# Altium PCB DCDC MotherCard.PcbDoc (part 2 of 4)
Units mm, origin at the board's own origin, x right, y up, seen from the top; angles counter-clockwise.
Board outline 252.5 x 130 mm, 6 copper layers (Top Layer, Layer 2, Layer 3, Layer 4, Layer 5, Bottom Layer), stack 1.582 mm thick; 322 components, 189 nets, 1077 pads, 1461 vias.
Unrouted connection lines stored in the file: 2.
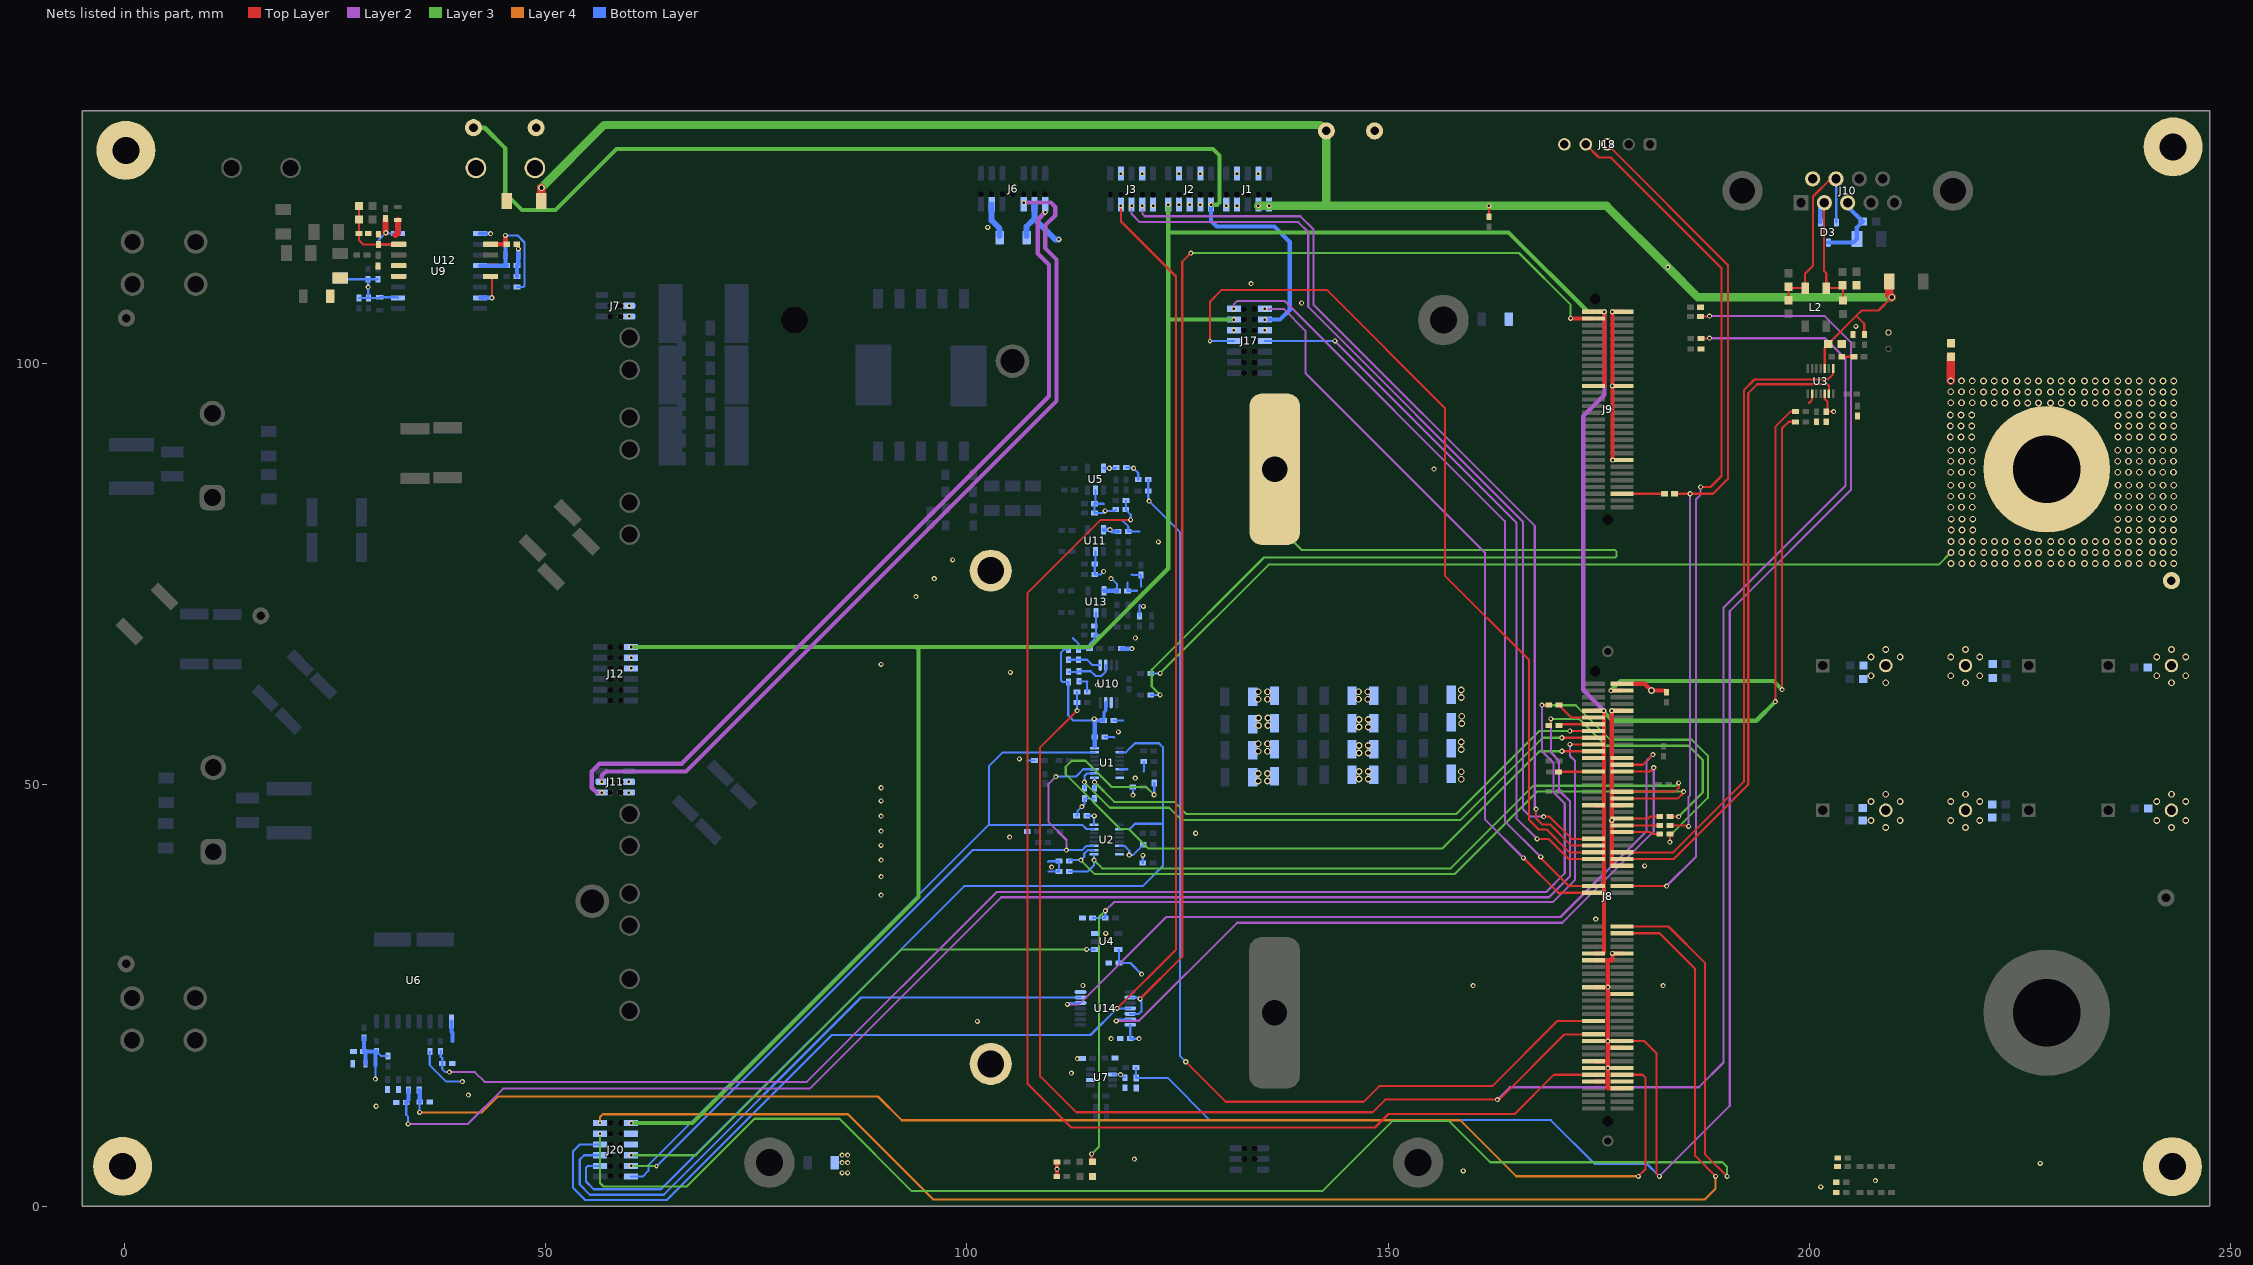
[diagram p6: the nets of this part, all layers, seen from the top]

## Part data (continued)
C41 C75 C80 C83: library part CMP-0076705-3, "CAP, CERM, 1 µF, 25 V,+/- 10%, X7R, AEC-Q200 Grade 1, 0603", Cap_Case=1.6x0.8x0.8mm, Manufacturer=TDK, Supplier Part Number 1=445-6931-1-ND, TempCo=X7R, Tolerance_%=10%, Value2=25V, ValueDisplayed=1µF
C46 C47 C72: library part CMP-0124726-1, "1 µF ±20% 700V Ceramic Capacitor Stacked SMD, 4 J-Lead", Digikey Part Number=495-B58035U7105M052CT-ND, Manufacturer=TDK, Mouser Part Number=871-B58035U7105M052, Operating Temperature Range="-40°C to +150°C", Tolerance_%=20%, ValueDisplayed=1uF
C51 C69 C70 C71 C81 C82 C85 C100 C104 C107 C108: library part CMP-0006357-2, "CAP, CERM, 2200 pF, 50 V, +/- 10%, X7R, AEC-Q200 Grade 1, 0402", Cap_Case=0402, Manufacturer=MuRata, Supplier Part Number 1=490-4914-1-ND, TempCo=X7R, Tolerance_%=10%, Value1=Unknown, Value2=50V, ValueDisplayed=2200pF
C73 C86 C97: library part CMP-0006324-2, "CAP, CERM, 0.01 uF, 50 V, +/- 10%, X7R, AEC-Q200 Grade 1, 0402", Cap_Case=0402, Manufacturer=TDK, Supplier Part Number 1=445-6893-1-ND, TempCo=X7R, Tolerance_%=10%, Value1="0.333065 ohm", Value2=50V, ValueDisplayed=0.01uF
D1: library part CMP-0002842-2, "LED, Red, SMD", Color=red, Manufacturer=Lite-On, Power_TotalModule=62.5mW, Value1=0.0625W, Value2=2V
D2: library part CMP-0002827-3, "LED, Green, SMD", Color=green, Manufacturer=Lite-On, Power_TotalModule=100mW, Value1=0.1W, Value2=2.1V
D3: library part CMP-0005919-2, "Diode, TVS, Bi, 24 V, SOT-23", Manufacturer="ON Semiconductor", Power_W=350mW, Supplier Part Number 1=NUP2105LT1GOSCT-ND, Value1=0.35W
D4 D5: library part CMP-0028855-2, "Diode, Schottky, 40 V, 3 A, AEC-Q101, SMAF", Manufacturer="Fairchild Semiconductor", Value1=3A, Value2=0.5V
D6 D7 D8 D9: library part CMP-0094495-1, "Diode Schottky 30 V 1A Surface Mount SOD-123", Digikey Part Number=MBR130T3GOSCT-ND, Forward Current=1A, Manufacturer=onsemi, Max Surge Forward Current=5.5A, Mouser Part Number=863-MBR130T3G, Operating Temperature Range="-65°C to +125°C", Peak Reverse Current=60uA
D10: library part CMP-0005910-2, "Diode, Zener, 4.7 V, 150 mW, AEC-Q101, SOD-523", Manufacturer=Rohm, Power_W=150mW, Supplier Part Number 1=78Y8306, Value1=0.15W
D11 D12 D13 D14: library part CMP-0028768-3, "Diode, Schottky, 30 V, 0.2 A, AEC-Q101, SOD-523", Manufacturer="ON Semiconductor", Value1=0.2A, Value2=0.5V
J1 J2 J3: library part CMP-0088850-1, "10 Position Receptacle Connector  Surface Mount", Current_A=2.9A, Digikey Part Number=SAM1226-05-ND, Manufacturer=SAMTEC, Mouser Part Number=200-FLE10501GDV, Operating Temperature Range="-55°C to +125°C"
J4 J5: library part CMP-0055125-1, "TERMINAL SCREW PC 30AMP, TH", Manufacturer=Keystone, Supplier Part Number 1=36-8199-ND
J6 J17: library part CMP-0075566-1, "Receptacle, 1.27mm, 7x2, Gold, SMT", Manufacturer=Samtec, Supplier Part Number 1=SAM1226-07-ND
J7 J11 J13: library part CMP-0055704-1, "Receptacle, 1.27mm, 3x2, Gold, SMT", Color=Black, Current_A=3.3A, Manufacturer=Samtec, Supplier Part Number 1=SAM1154-03-ND, Voltage_V=240V
J8: library part CMP-0003814-2, "C2000 controlCARD-120HSEC connector, SMT", Manufacturer=Samtec
J9: library part CMP-0003859-2, "C2000 controlCARD-180HSEC (60-pin addon) connector, SMT", Manufacturer=Samtec
J10: library part CMP-0074955-1, "CONN DB9 FEMALE R/A SOLDER TH", Manufacturer=NorComp, Supplier Part Number 1=182-909FE-ND
J12 J20: library part CMP-0075577-1, "Receptacle, 1.27mm, 6x2, Gold, SMT", Current_A=2A, Manufacturer=Samtec, Supplier Part Number 1=99P6807
J18: library part CMP-0054624-1, "Header, 2.54mm, 5x1, Gold, R/A, TH", Color=Black, Current_A=3A, Manufacturer="Sullins Connector Solutions", Supplier Part Number 1=S1111EC-05-ND
L1: library part CMP-0003317-1, "Ferrite Bead, 600 ohm @ 100 MHz, 0.5 A, 0402", Manufacturer=MuRata, Supplier Part Number 1=490-5441-1-ND, Value1="0.34 ohm", Value2=0.5A, ValueDisplayed="600 ohm"
L2: library part CMP-0062430-2, "Inductor, Ferrite, 100 uH, 0.15 A, 2 ohm, SMD", Manufacturer=TDK, Supplier Part Number 1=445-3959-1-ND, Value1="2 ohm", Value2=0.15A, ValueDisplayed=100uH
LBL1: library part CMP-0003625-1, "Thermal Transfer Printable Labels, 0.650\" W x 0.200\" H - 10,000 per roll", Manufacturer=Brady, Supplier Part Number 1=97C5133
Logo1: library part CMP-0074844-1
LOGO2: library part CMP-0074835-1, "IEC 61010-1 High Voltage Warning"
Logo3: library part CMP-0074847-1, "FCC_disclaimer"
Logo4: library part CMP-0074769-1
LOGO5 LOGO6: library part CMP-0074837-1, "IEC 61010-1 Hot Surface Warning"
R1 R15 R16 R19 R26 R117 R118 R120 R121 R122 R123 R124 R126 R127 R128 R129 R132 R133: library part CMP-0080698-1, "RES, 0, 0%, 1 W, AEC-Q200 Grade 0, 2512", Manufacturer=Kamaya, Power_W=1W, Supplier Part Number 1=791-RMC1JPTE, Tolerance_%=0%, Value_Code=0
R2 R3: library part CMP-0018576-3, "RES, 10 k, 5%, 0.25 W, AEC-Q200 Grade 0, 1206", Manufacturer=Vishay-Dale, Power_W=250mW, Supplier Part Number 1=541-10KECT-ND, TempCo="200 ppm/C", Tolerance_%=5%, Value2=0.25W, Value_Code=10k0, ValueDisplayed=10k
R4 R5 R6 R7: library part CMP-0018574-3, "RES, 100 k, 5%, 0.25 W, AEC-Q200 Grade 0, 1206", Manufacturer=Vishay-Dale, Power_W=250mW, Supplier Part Number 1=541-100KECT-ND, TempCo="200 ppm/C", Tolerance_%=5%, Value2=0.25W, Value_Code=100k
R8 R9 R54 R78: library part CMP-0026786-1, "RES, 7.50 k, 0.1%, 0.063 W, AEC-Q200 Grade 0, 0402", Manufacturer=Panasonic, Power_W=63mW, Supplier Part Number 1=P7.5KDCCT-ND, TempCo="25 ppm/C", Tolerance_%=0.1%, Value2=0.063W, Value_Code=7k50, ValueDisplayed=7.50k
R10 R12 R13 R41 R46 R48 R49 R51 R53 R55 R57 R63 R64 R68 R70 R71 R72 R80 R82 R83 R98 R107: library part CMP-0026822-3, "RES, 0, 5%, 0.063 W, AEC-Q200 Grade 0, 0402", Manufacturer=Vishay-Dale, Power_W=63mW, Supplier Part Number 1=541-0.0JCT-ND, TempCo="200 ppm/C", Tolerance_%=5%, Value2=0.063W, Value_Code=0000, ValueDisplayed=0
R11 R17 R22: library part CMP-0023343-3, "RES, 0, 1%, 0.1 W, AEC-Q200 Grade 0, 0603", Manufacturer="Stackpole Electronics Inc", Power_W=100mW, Supplier Part Number 1=RMCF0603ZT0R00CT-ND, TempCo=ppm/C, Tolerance_%=1%, Value2=0.1W, Value_Code=0
R14 R50 R60 R61 R65 R66 R79 R97 R99 R100 R103 R130 R134 R135 R136 R137: library part CMP-0026748-1, "RES, 10.0 k, 1%, 0.063 W, AEC-Q200 Grade 0, 0402", Manufacturer="KOA Speer", Power_W=63mW, Supplier Part Number 1=660-RK73H1ETTP1002F, TempCo="100 ppm/C", Tolerance_%=1%, Value2=0.063W, Value_Code=10k0, ValueDisplayed=10.0k
R18 R21: library part CMP-0022532-4, "RES, 60.4 k, 1%, 0.1 W, AEC-Q200 Grade 0, 0603", Manufacturer=Vishay-Dale, Power_W=100mW, Supplier Part Number 1=541-60.4KHCT-ND, TempCo="100 ppm/C", Tolerance_%=1%, Value2=0.1W, Value_Code=60k4, ValueDisplayed=60.4k
R20 R33 R77 R119: library part CMP-0093609-1, "0Ω ±0 0.25W 1206 Thick Film Chip Resistor AEC-Q200 compliant", Manufacturer="Stackpole Electronics", Operating Temperature Range="-55°C to +155°C", Power_W=250mW
R23: library part CMP-0022138-4, "RES, 1.00 M, 1%, 0.1 W, AEC-Q200 Grade 0, 0603", Manufacturer=Vishay-Dale, Power_W=100mW, Supplier Part Number 1=541-1.00MHCT-ND, TempCo="100 ppm/C", Tolerance_%=1%, Value2=0.1W, Value_Code=1M00, ValueDisplayed=1.00M
R24 R32 R101 R102: library part CMP-0026676-1, "RES, 2.00 k, 1%, 0.1 W, AEC-Q200 Grade 0, 0402", Manufacturer=Panasonic, Power_W=100mW, Supplier Part Number 1=P2.00KLCT-ND, TempCo="100 ppm/C", Tolerance_%=1%, Value2=0.1W, Value_Code=2k00, ValueDisplayed=2.00k
R25 R31 R67 R87 R96 R114: library part CMP-0026071-3, "RES, 1.00 k, 1%, 0.063 W, AEC-Q200 Grade 0, 0402", Manufacturer=Vishay-Dale, Power_W=63mW, Supplier Part Number 1=541-1.00KLCT-ND, TempCo="100 ppm/C", Tolerance_%=1%, Value2=0.063W, Value_Code=1k00, ValueDisplayed=1.00k
R27 R40 R47 R52 R62 R73 R74 R76 R112 R113: library part CMP-0026764-1, "RES, 10.0, 1%, 0.063 W, AEC-Q200 Grade 0, 0402", Manufacturer="Stackpole Electronics Inc", Power_W=63mW, Supplier Part Number 1=RMCF0402JT10R0CT-ND, TempCo="100 ppm/C", Tolerance_%=1%, Value2=0.063W, Value_Code=10R0, ValueDisplayed=10.0
R28 R29 R39: library part CMP-0016648-3, "RES, 15.0, 1%, 0.25 W, AEC-Q200 Grade 0, 1206", Manufacturer=Vishay-Dale, Power_W=250mW, Supplier Part Number 1=541-15.0FCT-ND, TempCo="100 ppm/C", Tolerance_%=1%, Value2=0.25W, Value_Code=15R0, ValueDisplayed=15.0
R30 R37 R38: library part CMP-0022268-4, "RES, 2.00 k, 1%, 0.1 W, AEC-Q200 Grade 0, 0603", Manufacturer=Vishay-Dale, Power_W=100mW, Supplier Part Number 1=541-2.00KHCT-ND, TempCo="100 ppm/C", Tolerance_%=1%, Value2=0.1W, Value_Code=2k00, ValueDisplayed=2.00k
R34 R35 R36 R110 R115 R125 R131: library part CMP-0025951-3, "RES, 100, 1%, 0.063 W, AEC-Q200 Grade 0, 0402", Manufacturer=Vishay-Dale, Power_W=63mW, Supplier Part Number 1=541-100LCT-ND, TempCo="100 ppm/C", Tolerance_%=1%, Value2=0.063W, Value_Code=100R, ValueDisplayed=100
R42: library part CMP-0026395-2, "RES, 47.5 k, 1%, 0.063 W, AEC-Q200 Grade 0, 0402", Manufacturer=Vishay-Dale, Power_W=63mW, Supplier Part Number 1=541-47.5KLCT-ND, TempCo="100 ppm/C", Tolerance_%=1%, Value2=0.063W, Value_Code=47k5, ValueDisplayed=47.5k
R43 R44 R45 R104 R105 R106: library part CMP-0017741-3, "RES, 845 k, 1%, 0.25 W, AEC-Q200 Grade 0, 1206", Manufacturer=Panasonic, Power_W=250mW, Supplier Part Number 1=P845KFCT-ND, TempCo="100 ppm/C", Tolerance_%=1%, Value2=0.25W, Value_Code=845k
R56 R108: library part CMP-0017234-3, "RES, 9.09 k, 1%, 0.25 W, AEC-Q200 Grade 0, 1206", Manufacturer=Vishay-Dale, Power_W=250mW, Supplier Part Number 1=541-9.09KFCT-ND, TempCo="100 ppm/C", Tolerance_%=1%, Value2=0.25W, Value_Code=9k09, ValueDisplayed=9.09k
R58 R59 R69 R75 R109 R116: library part CMP-0026027-3, "RES, 15.0 k, 1%, 0.063 W, AEC-Q200 Grade 0, 0402", Manufacturer=Vishay-Dale, Power_W=63mW, Supplier Part Number 1=541-15.0KLCT-ND, TempCo="100 ppm/C", Tolerance_%=1%, Value2=0.063W, Value_Code=15k0, ValueDisplayed=15.0k
R81: library part CMP-0026404-2, "RES, 49.9, 1%, 0.063 W, AEC-Q200 Grade 0, 0402", Manufacturer=Vishay-Dale, Power_W=63mW, Supplier Part Number 1=541-49.9LCT-ND, TempCo="100 ppm/C", Tolerance_%=1%, Value2=0.063W, Value_Code=49R9, ValueDisplayed=49.9
R91 R95: library part CMP-0026750-1, "RES, 3.30 k, 1%, 0.063 W, AEC-Q200 Grade 0, 0402", Manufacturer="KOA Speer", Power_W=63mW, Supplier Part Number 1=660-RK73H1ETTP3301F, TempCo="100 ppm/C", Tolerance_%=1%, Value2=0.063W, Value_Code=3k30, ValueDisplayed=3.30k
R92 R111: library part CMP-0026337-2, "RES, 3.65 k, 1%, 0.063 W, AEC-Q200 Grade 0, 0402", Manufacturer=Vishay-Dale, Power_W=63mW, Supplier Part Number 1=541-3.65KLCT-ND, TempCo="100 ppm/C", Tolerance_%=1%, Value2=0.063W, Value_Code=3k65, ValueDisplayed=3.65k
R93: library part CMP-0078244-2, "RES, 30.0 k, 1%, 0.063 W, AEC-Q200 Grade 0, 0402", Manufacturer=Vishay-Dale, Power_W=63mW, Supplier Part Number 1=541-30.0KLCT-ND, TempCo="100 ppm/C", Tolerance_%=1%, Value2=0.063W, Value_Code=30k0, ValueDisplayed=30.0k
R94: library part CMP-0025950-3, "RES, 100 k, 1%, 0.063 W, AEC-Q200 Grade 0, 0402", Manufacturer=Vishay-Dale, Power_W=63mW, Supplier Part Number 1=541-100KLCT-ND, TempCo="100 ppm/C", Tolerance_%=1%, Value2=0.063W, Value_Code=100k
T1: library part CMP-0085494-1, "Current Sense Transformer, 8.5 mH, 254 Vµs, 40 A, AEC-Q200 Grade 1, SMT", Manufacturer=FANGCHENG, ValueDisplayed=8.5mH
TP3 TP4: library part CMP-0003719-1, "Testpoint", Manufacturer="Texas Instruments"
U1 U2: library part CMP-0860825-3, "5-V, Bidirectional 8:1, 1-Channel and 4:1, 2-Channel Multiplexers with Current Injection Control, DYY0016A (SOT-23-THIN-16)", Alternate Manufacturer="Texas Instruments"
U3: library part CMP-0089855-1, "Low-Power Fault Protected CAN FD Transceiver with INH and WAKE", Manufacturer="Texas Instruments", Max Supply Voltage=28V, Min Supply Voltage=1.7V, Operating Temperature Range="-40°C to +125°C"
U4: library part CMP-0051573-2, "Automotive Catalog Single 2-Input Positive-AND Gate, DBV0005A (SOT-23-5)", F @ Nom Voltage(Max)(Mhz)=75, Generic Part Number=SN74AHC1G08-Q1, ICC @ Nom Voltage(Max)(mA)=0.01, Manufacturer="Texas Instruments", Operating Temperature Range="-40 to 125 C", Rating=Automotive, tpd @ Nom Voltage(Max)(ns)=12.3,7.9, Voltage(Nom)(V)=3.3,5
U5: library part CMP-0121215-2, "Automotive 50-MHz single-supply operational amplifier with rail-to-rail input and output 5-SOT-23 -40 to 125", Digikey Part Number=296-TLV365QDBVRQ1CT-ND, Input Bias Current=0.000005uA, Input Offset Voltage=0.4mV, Manufacturer="Texas Instruments", Max Supply Voltage=5.5V, Min Supply Voltage=2.2V, Mouser Part Number=595-TLV365QDBVRQ1, Nominal Supply Current=4.6mA, Operating Temperature Range="-40°C to +125°C", Output Current Per Channel=85mA, Voltage Gain=120dB
U6: library part CMP-0097985-1, Manufacturer="Texas Instruments", Operating Temperature Range=to
U7: library part CMP-0121413-1, "AEC-Q100, -5-V to 110-V, bidirectional, 1.1-MHz 8-V/µs ultraprecise current sense amplifier", Digikey Part Number=296-INA296A4QDDFRQ1TR-ND, Input Bias Current=35uA, Input Offset Voltage=0.003mV, Manufacturer="Texas Instruments", Max Supply Voltage=20V, Min Supply Voltage=2.7V, Mouser Part Number=595-INA296A4QDDFRQ1, Nominal Supply Current=2.5mA, Operating Temperature Range="-40°C to +125°C", Voltage Gain=0.1V/mV
U9: library part CMP-0121212-1, "Automotive, 0 to 2-V input, precision reinforced isolated amplifier with integrated DC/DC converter 16-SOIC -40 to 125", Digikey Part Number=296-AMC3311QDWERQ1CT-ND, Input Bias Current=0.0035uA, Input Offset Voltage=0.1mV, Manufacturer="Texas Instruments", Max Supply Voltage=5.5V, Min Supply Voltage=3V, Mouser Part Number=595-AMC3311QDWERQ1, Nominal Supply Current=28.5-36.5mA, Operating Temperature Range="-40°C to +125°C", Output Current Per Channel=14mA, Voltage Gain=0.001V/mV
U10: library part CMP-0065433-2, "Automotive, 36-V Prog. Gain, Bi-Directional, Zero-Drift, High-Speed Voltage Out Current Sense Amp, DGK0008A (VSSOP-8)", Alternate Manufacturer="Texas Instruments"
U11 U13: library part CMP-0120546-1, "Automotive, single-channel, 5.5-V 1-MHz rail-to-rail input and output operational amplifier 5-SOT-23 -40 to 125", Digikey Part Number=296-TLV9001QDBVRQ1CT-ND, Input Bias Current=0.000005uA, Input Offset Voltage=0.4mV, Manufacturer="Texas Instruments", Max Dual Supply Voltage=2.75V, Max Supply Voltage=5.5V, Min Dual Supply Voltage=900mV, Min Supply Voltage=1.8V, Mouser Part Number=595-TLV9001QDBVRQ1, Nominal Supply Current=60uA, Operating Temperature Range="-40°C to +125°C", Output Current Per Channel=40mA, Voltage Gain=130dB
U12: library part CMP-0090465-1, "Automotive 2-V input, reinforced isolated amplifier with high CMTI for voltage sensing 8-SOIC -40 to 125", Digikey Part Number=296-50938-1-ND, Input Bias Current=0.0035uA, Input Offset Voltage=-1.1mV, Manufacturer="Texas Instruments", Max Supply Voltage=5.5V, Min Supply Voltage=3V, Mouser Part Number=595-AMC1311BQDWVRQ1, Nominal Supply Current=5.3-7.1mA, Operating Temperature Range="-40°C to +125°C", Output Current Per Channel=13mA
U14: library part CMP-0054481-1, "Automotive Catalog Quadruple 2-Input Positive-AND Gate, PW0014A, LARGE T&R", F @ Nom Voltage(Max)(Mhz)=110, Generic Part Number=SN74AHC08Q-Q1, ICC @ Nom Voltage(Max)(mA)=0.02, Manufacturer="Texas Instruments", Operating Temperature Range(C)="-40 to 125", Rating=Automotive, tpd @ Nom Voltage(Max)(ns)=14,9, Voltage(Nom)(V)=3.3,5
ZZ1: library part CMP-0003616-3
ZZ2: library part CMP-0077236-1
ZZ3: library part CMP-0077237-1
ZZ4: library part CMP-0077238-1

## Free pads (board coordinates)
  round 7 hole 3.2: 1(-0.2,4.75) 1(0.175,125.325) 1(243.05,4.7) 1(243.15,125.725)
  round 4 hole 2.8: 1(55.525,36.2) 1(105.403,100.312)
  round 6 hole 3.2: 1(76.55,5.175) 1(153.55,5.175) 1(156.55,105.175)
  round 3.2 hole 3.2: 1(79.55,105.175)
  round 5 hole 3.2: 1(102.825,16.9) 1(102.825,75.434)
  round 15 hole 8: 1(228.15,22.975) 1(228.15,87.475)
  rrect50% 6x18 hole 3 square: 2(136.5,22.975) 2(136.525,87.475)
  round 0.7 hole 0.7: 3(57.665,49.105) 3(57.665,50.375) 3(57.673,105.6) 3(57.673,106.87) 3(57.689,3.575) 3(57.689,4.795) 3(57.689,6.065) 3(57.689,7.335) 3(57.689,8.605) 3(57.689,9.875) 3(57.689,60.025) 3(57.689,61.295) 3(57.689,62.565) 3(57.689,63.835) 3(57.689,65.105) 3(57.689,66.375) 3(58.886,49.105) 3(58.886,50.375) 3(58.894,105.6) 3(58.894,106.87) 3(58.91,3.575) 3(58.91,4.795) 3(58.91,6.065) 3(58.91,7.335) 3(58.91,8.605) 3(58.91,9.875) 3(58.91,60.025) 3(58.91,61.295) 3(58.91,62.565) 3(58.91,63.835) 3(58.91,65.105) 3(58.91,66.375) 3(101.665,120.125) 3(102.935,120.125) 3(104.205,120.125) 3(105.475,120.125) 3(106.745,120.125) 3(108.015,120.125) 3(109.285,120.125) 3(117.01,120.075) 3(118.28,120.075) 3(119.55,120.075) 3(120.82,120.075) 3(122.09,120.075) 3(123.895,120.075) 3(125.165,120.075) 3(126.435,120.075) 3(127.705,120.075) 3(128.975,120.075) 3(130.78,120.075) 3(132.05,120.075) 3(132.89,98.885) 3(132.89,100.155) 3(132.89,101.425) 3(132.89,102.695) 3(132.89,103.965) 3(132.89,105.235) 3(132.89,106.505) 3(132.922,5.61) 3(132.922,6.88) 3(133.32,120.075) 3(134.141,98.885) 3(134.141,100.155) 3(134.141,101.425) 3(134.141,102.695) 3(134.141,103.965) 3(134.141,105.235) 3(134.141,106.505) 3(134.143,5.61) 3(134.143,6.88) 3(134.59,120.075) 3(135.86,120.075)

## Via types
v1: diameter 0.8, hole 0.5, Top Layer to Bottom Layer, 1187 vias
v2: diameter 0.6, hole 0.3, Top Layer to Bottom Layer, 259 vias
v3: diameter 0.508, hole 0.254, Top Layer to Bottom Layer, 13 vias
v4: diameter 4.5, hole 4.5, Top Layer to Bottom Layer, 2 vias

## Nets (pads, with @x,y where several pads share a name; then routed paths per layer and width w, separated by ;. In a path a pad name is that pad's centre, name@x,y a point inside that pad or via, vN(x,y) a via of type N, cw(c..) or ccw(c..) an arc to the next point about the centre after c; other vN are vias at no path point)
3V3: C19.1 C22.1 C29.1 C42.1 C53.1 C75.1 C76.1 C82.1 C83.1 C88.1 C89.1 C96.1 C99.1 C105.1 C106.1 J8.119 L1.1 R8.2 R9.2 R14.2 R41.1 R42.1 R46.1 R50.2 R58.2 R78.2 R79.2 R103.2 R111.1 R130.2 U1.16 U2.16 U3.5 U4.5 U5.5 U7.6 U9.12 U10.3 U11.5 U12.8 U13.5 U14.14 | length 85.1
  Top Layer w0.254: U3.5@201.8,96.425 201.8,95.825 201.823,95.802 201.823,95.794 202.141,95.475 202.141,94.449 202.287,94.303 v2(202.866,94.303)
  Top Layer w0.5: U12.8@43.468,114.171 C96.1@45.381,114.171 45.219,114.332 v2(45.219,115.225) ; R9.2@110.649,3.523 110.686,3.56 R8.2@110.686,5.279 ; J8.119@177.754,62.006 180.444,62.006 v1(181.244,61.206) 182.815,61.206 R50.2@183.015,61.006
  Bottom Layer w0.254: v2(29.793,15.095) 29.793,16.663 29.807,16.677 ; L1.1@29.923,18.4 30.498,17.825 R111.1@31.3,17.825 ; R103.2@36.25,18.362 36.25,16.749 38.202,14.797 v2(40.124,14.797) ; v2(45.219,115.225) 46.655,115.225 47.493,114.387 47.493,109.216 47.363,109.086 R42.1@46.593,109.086 ; R46.1@112.052,66.06 111.496,66.06 111.147,65.711 111.147,62.462 111.387,62.222 R41.1@112.074,62.222 112.016,62.164 112.016,58.272 112.635,57.653 v2@115.163,57.653 ; C105.1@114.212,46.346 v2@115.135,46.346 ; U2.16@115.087,45.269 115.087,46.298 v2@115.135,46.346 ; v2@115.185,46.396 v2@115.135,46.346 ; U5.5@116.209,87.588 117.61,87.588 C29.1@117.708,87.685 ; v2(117.097,74.484) 117.182,74.484 117.794,73.872 117.794,73.113 C88.1@117.864,73.043 ; U7.6@117.269,15.632 118.378,15.632 C42.1@118.743,15.267 ; U4.5@117.947,30.493 118.041,30.399 C19.1@118.041,28.865 119.409,28.865 v2(120.723,27.55) ; U14.14@119.377,21.533 119.377,19.9 C89.1@119.389,19.889 v2(120.429,19.889) ; v2(119.69,48.8) R130.2@119.69,49.764 ; R14.2@120.869,40.735 120.869,41.62 v2(120.89,41.64)
  Bottom Layer w0.4: C53.1@116.209,57.672 116.268,57.731 116.268,58.631 116.473,58.836 U10.3@116.473,59.769
  Bottom Layer w0.5: R79.2@28.43,19.994 28.43,18.4 C76.1@28.395,18.365 ; C75.1@28.631,16.925 28.631,18.129 C76.1@28.395,18.365 ; 29.807,16.677 29.807,18.284 L1.1@29.888,18.365 ; L1.1@29.923,18.4 L1.1@29.888,18.365 ; U9.12@42.218,111.626 C82.1@45.4,111.626 45.238,111.788 C83.1@45.238,112.896 45.238,115.206 v2(45.219,115.225) ; 115.157,54.572 115.163,54.577 115.163,57.653 116.19,57.653 C53.1@116.209,57.672 ; U11.5@116.205,80.297 v2(116.977,80.297) 117.18,80.094 C99.1@117.944,80.094 ; U13.5@116.282,73.043 C88.1@117.864,73.043 ; R78.2@118.339,66.178 v2(119.569,66.178) ; C76.1@28.395,18.365 L1.1@29.888,18.365
  other v2: 110.686,4.42 118.223,15.632 113.095,17.53 115.111,46.322 115.111,57.837 116.909,87.588
5V0: J2.10 J8.48 J8.84 J8.98 J8.112 J9.158 J9.180 J12.11 J17.12 J20.11 R80.2 | length 401.4
  Top Layer w0.254: v2(195.943,59.888) 195.943,92.519 197.762,94.338 R80.2@198.338,94.338
  Top Layer w0.5: J8.48@174.354,30.006 175.508,30.006 175.596,30.094 J8.84@175.596,47.606 ; J8.84@174.354,47.606 J8.84@175.596,47.606 ; J8.98@174.354,53.206 J8.98@175.596,53.206 ; J8.112@174.354,58.806 v2(175.596,58.806) J8.98@175.596,53.206 ; J9.158@174.354,97.363 175.647,97.363 v2(175.647,106.163) J9.180@174.354,106.163 ; J8.84@175.596,47.606 J8.98@175.596,53.206
  Layer 2 w0.5: v2(175.596,58.806) 173.139,61.263 173.139,93.797 175.647,96.306 v2(175.647,106.163)
  Layer 3 w0.5: v2(60.143,9.875) 67.422,9.875 94.243,36.696 94.243,66.082 93.95,66.375 ; v2(60.143,66.375) 93.95,66.375 ; v2(123.895,118.87) 123.895,115.575 ; v2(131.675,105.235) 123.895,105.235 ; v2(175.596,58.806) 175.596,58.671 176.642,57.625 193.679,57.625 v2(195.943,59.888) ; v2(175.647,106.163) 173.693,106.163 164.282,115.575 123.895,115.575 ; 93.95,66.375 114.589,66.375 123.895,75.681 123.895,105.235 ; 123.895,105.235 123.895,115.575
5V0_CAN: J8.117 R10.2 | length 55.5
  Top Layer w0.254: v2(196.735,61.325) 196.735,92.325 197.514,93.103 R10.2@198.338,93.103
  Top Layer w0.5: v2(176.412,61.206) J8.117@177.754,61.206
  Layer 3 w0.5: v2(176.412,61.206) 177.552,62.346 195.715,62.346 v2(196.735,61.325)
12V: 12V.1 J2.2 J17.11 | length 129.5
  Layer 3 w0.5: 12V.1@41.438,128 42.773,128 45.219,125.553 45.219,120.201 47.2,118.22 51.17,118.22 58.425,125.475 129.209,125.475 129.987,124.697 129.987,120.413 129.98,120.406 129.98,119.13 129.72,118.87 v2(128.975,118.87)
  Bottom Layer w0.5: v2(128.975,118.87) 128.975,116.947 129.652,116.27 136.491,116.27 138.311,114.45 138.311,106.385 137.161,105.235 v2(135.36,105.235)
A0: J8.85 R134.2 U2.10 | length 87.7
  Top Layer w0.254: J8.85@177.754,48.406 184.4,48.406 185.044,49.05 v2(185.044,49.206)
  Layer 3 w0.254: v2(113.519,41.075) 115.169,39.425 157.869,39.425 167.649,49.206 v2(185.044,49.206)
  Bottom Layer w0.254: R134.2@112.131,40.956 112.25,41.075 v2(113.519,41.075) 113.928,41.484 113.928,41.86 114.337,42.269 U2.10@115.087,42.269
A1: J8.87 R135.2 U2.9 | length 86
  Top Layer w0.254: J8.87@177.754,49.206 184.002,49.206 184.47,49.674 v2(184.47,50.249)
  Layer 3 w0.254: v2(115.087,41.075) 116.062,40.1 157.411,40.1 167.217,49.906 184.128,49.906 v2(184.47,50.249)
  Bottom Layer w0.254: R135.2@112.131,39.725 114.332,39.725 115.087,40.48 v2(115.087,41.075) U2.9@115.087,41.769
A2: J8.104 R136.2 U1.10 | length 69.1
  Top Layer w0.254: v2(170.598,55.606) J8.104@174.354,55.606
  Layer 3 w0.254: v2(113.932,50.332) 116.962,47.302 123.997,47.302 125.474,45.826 158.539,45.826 168.319,55.606 v2(170.598,55.606)
  Bottom Layer w0.254: R136.2@113.932,49.604 v2(113.932,50.332) 113.932,51.059 114.243,51.369 U1.10@115.139,51.369
A3: J8.106 R137.2 U1.9 | length 66.1
  Top Layer w0.254: v2(171.567,56.406) J8.106@174.354,56.406
  Layer 3 w0.254: v2(115.139,50.346) 117.487,47.998 124.599,47.998 126.041,46.556 158.052,46.556 167.902,56.406 v2(171.567,56.406)
  Bottom Layer w0.254: U1.9@115.139,50.869 v2(115.139,50.346) 115.139,49.623 R137.2@115.157,49.604
ACL1_PWM: J8.58 J17.13 | length 89.2
  Top Layer w0.254: v2(166.045,41.337) 170.177,37.206 J8.58@174.354,37.206
  Layer 2 w0.254: v2(135.36,106.505) 137.578,106.505 140.165,103.918 140.165,98.885 161.467,77.583 161.467,45.915 v2(166.045,41.337)
ACL2_PWM: J8.60 J17.14 | length 93.1
  Top Layer w0.254: v2(168.097,41.456) 168.097,41.337 171.429,38.006 J8.60@174.354,38.006
  Layer 2 w0.254: v2(131.675,106.505) 131.675,107.036 132.098,107.458 137.69,107.458 163.842,81.307 163.842,45.711 v2(168.097,41.456)
AGND: AGND.1 BIAS_DGND.1 C19.2 C20.2 C21.2 C22.2 C23.2 C29.2 C30.2 C35.2 C42.2 C51.2 C52.2 C53.2 C54.2 C69.2 C70.2 C71.2 C73.2 C75.2 C76.2 C77.2 C78.2 C82.2 C83.2 C88.2 C89.2 C90.2 C91.2 C92.2 C93.2 C94.2 C96.2 C99.2 C100.2 C101.2 C102.2 C103.2 C104.2 C105.2 C106.2 C107.2 C108.2 D2.2 D3.3 J1.1 J1.3 J1.4 J1.8 J2.3 J2.4 J2.6 J2.7 J2.8 J3.4 J3.8 J3.9 J8.7 J8.10 J8.13 J8.16 J8.19 J8.22 J8.35 J8.38 J8.46 J8.47 J8.65 J8.83 J8.97 J8.111 J9.135 J9.157 J9.179 J10.3 J10.6 J12.7 J12.9 J17.9 J17.10 J18.5 J20.7 J20.9 pad.1@102.825,16.9 pad.1@102.825,75.434 R11.2 R23.1 R32.1 R48.2 R49.1 R54.1 R69.1 R75.1 R87.1 R94.1 R96.1 R101.1 R102.1 R114.1 R116.1 R134.1 R135.1 R136.1 R137.1 TP4.1 U1.6 U1.8 U2.6 U2.8 U3.2 U4.3 U5.2 U6.3 U7.2 U9.9 U9.15 U10.2 U11.2 U12.5 U13.2 U14.7 | length 147.9
  Top Layer w0.254: U12.5@43.468,110.361 43.619,110.211 v2(43.619,107.826) ; 199.925,95.325 200.3,95.7 U3.2@200.3,96.425
  Top Layer w0.5: J8.10@174.354,14.806 176.054,14.806 ; J8.16@174.354,17.206 176.054,17.206 ; J8.22@174.354,19.606 v2(176.054,19.606) ; J8.38@174.354,26.006 v2(176.054,26.006) ; J8.46@174.354,29.206 176.054,29.206 ; 176.054,14.006 J8.7@177.754,14.006 ; 176.054,14.123 176.054,14.806 ; J8.13@177.754,16.406 v2(176.054,16.406) ; J8.19@177.754,18.806 176.054,18.806 ; J8.35@177.754,25.206 176.054,25.206 ; J8.47@177.754,30.006 v2(176.6,30.006) 176.6,29.206 176.054,29.206 ; J8.65@177.754,40.406 176.522,40.406 J8.83@176.522,47.606 ; J8.83@177.754,47.606 J8.83@176.522,47.606 ; J8.97@177.754,53.206 176.649,53.206 J8.97@176.522,53.079 ; J8.111@177.754,58.806 v2(176.522,58.806) J8.97@176.522,53.079 ; J9.135@177.754,88.563 v2(176.624,88.563) 176.6,88.587 v2(176.6,97.363) ; J9.157@177.754,97.363 v2(176.6,97.363) ; J9.179@177.754,106.163 v2(176.6,106.163) v2(176.6,97.363) ; 176.054,14.806 v2(176.054,16.406) ; v2(176.054,16.406) 176.054,17.206 ; 176.054,17.206 176.054,18.806 ; 176.054,18.806 v2(176.054,19.606) ; v2(176.054,19.606) 176.054,25.206 ; 176.054,25.206 v2(176.054,26.006) ; v2(176.054,26.006) 176.054,29.206 ; J8.83@176.522,47.606 J8.97@176.522,53.079
  Bottom Layer w0.254: 107.168,52.89 C107.2@108.011,52.89 ; 109.615,40.877 109.694,40.956 R134.1@110.931,40.956 R135.1@110.931,39.725 109.694,39.725 ; 112.572,67.443 113.258,66.757 R49.1@113.258,66.06 113.376,66.178 R75.1@114.539,66.178 114.539,66.699 115.121,67.281 R69.1@115.121,67.783 ; C105.2@113.013,46.346 113.104,46.437 113.104,46.879 113.932,47.707 R136.1@113.932,48.404 R137.1@115.157,48.404 ; R48.2@113.301,62.302 114.309,62.302 114.266,62.259 C54.2@114.266,61.055 ; U11.2@115.255,77.697 115.255,76.306 R116.1@115.16,76.211 C102.2@115.16,74.993 115.884,74.993 v2(116.225,75.334) ; U5.2@115.259,84.988 115.259,83.494 R32.1@115.143,83.378 ; U13.2@115.332,70.443 115.332,67.994 R69.1@115.121,67.783 ; 116.123,67.783 R69.1@115.121,67.783 ; 116.268,83.33 116.219,83.378 R32.1@115.143,83.378 ; C106.2@116.363,55.678 117.426,55.678 117.475,55.629 ; C53.2@117.409,57.672 118.503,57.672 118.522,57.653 ; C30.2@117.654,82.668 117.507,82.52 v2(116.407,82.52) 116.165,82.278 C35.2@115.14,82.278 115.143,82.281 R32.1@115.143,83.378 ; U2.6@118.087,42.769 118.695,42.769 119.263,42.201 v2(119.263,41.675) 119.676,41.675 C71.2@120.909,42.908 ; U1.6@118.139,51.869 119.029,51.869 ; 118.477,81.358 119.144,80.691 C99.2@119.144,80.094 120.499,80.094 ; C29.2@118.908,87.685 119.675,87.685 v2(119.773,87.588) 120.331,87.03 C51.2@120.331,86.252 ; 119.042,74.039 119.064,74.017 C88.2@119.064,73.043 120.149,73.043 ; 119.527,74.993 119.606,74.913 C101.2@120.662,74.913 120.662,73.596 120.706,73.551 ; C90.2@120.499,70.055 120.499,71.338 120.529,71.368 ; 120.98,51.606 120.991,51.617 C108.2@120.991,52.806
  Bottom Layer w0.5: U6.3@38.813,21.925 38.813,20.712 38.931,20.594 38.931,19.6 ; U9.15@42.218,107.816 42.228,107.826 v2(43.619,107.826) ; U9.9@42.218,115.436 v2(43.468,115.436) ; C78.2@46.593,110.356 46.593,111.619 C82.2@46.6,111.626 46.762,111.788 C83.2@46.762,112.896 v2(46.762,113.617) ; D3.3@202.225,114.375 205.184,114.375 C23.2@205.609,114.8 205.609,116.17 R23.1@206.309,116.87 204.524,118.655 J10.3@204.524,119.095
  other v2: 201.325,2.3 207.816,3.051 158.9,4.2 227.375,5.1 119.863,5.595 29.888,11.869 40.832,13.188 112.393,15.808 117.111,19.889 101.25,21.95 160.075,26.2 182.616,26.2 113.75,26.202 116.473,32.393 174.623,34.087 89.825,36.928 89.825,39.117 110.04,40.246 180.424,40.406 89.825,41.075 89.825,42.834 105.059,43.801 127.15,44.269 89.825,44.533 176.522,45.805 89.825,46.312 113.65,47.425 89.825,48.103 89.825,49.673 119.971,50.82 106.225,53.1 117.977,56.289 115.478,61.858 105.15,63.361 60.143,63.835 89.825,64.312 60.143,65.105 119.978,67.443 120.931,71.195 93.95,72.359 96.117,74.494 98.294,76.725 122.708,78.852 155.429,87.475 131.675,103.965 135.36,103.965 205.508,104.421 139.729,107.199 133.717,109.508 122.09,118.725 130.78,118.725 132.05,118.725 125.165,118.87 126.435,118.87 127.705,118.87 118.274,122.555 120.814,122.555 125.165,122.555 127.705,122.555 132.05,122.555 134.59,122.555
AGNDM: J6.11 J11.4 J11.6 pad.3@58.886,49.105 pad.3@58.886,50.375 R20.1 | length 8
  Bottom Layer w0.7: R20.1@107.075,115.15 107.075,116.27 108.015,117.21 ; J6.11@108.015,118.87 108.015,117.21 ; v2(110.901,114.743) 110.482,114.743 108.015,117.21
  other v2: 59.89,49.105 59.89,50.375
AGNDP: C41.2 C44.2 C79.2 C80.2 C81.2 C84.2 C85.2 C86.2 C95.2 C97.2 D10.2 J6.3 J7.4 J7.6 pad.3@58.894,105.6 pad.3@58.894,106.87 R20.2 R56.1 R108.1 R119.2 U9.2 U9.7 U9.8 U12.3 U12.4 | length 24.9
  Top Layer w0.7: C95.2@30.168,115.351 C95.2@30.188,115.371 ; C44.2@30.993,117.222 30.993,115.583 v2(31.04,115.536) ; 32.148,115.269 32.314,115.436 32.462,115.436 C41.2@32.462,117.06
  Bottom Layer w0.254: R56.1@25.618,110.181 25.783,110.016 C84.2@28.943,110.016 ; C79.2@27.843,107.791 C81.2@28.968,107.791 ; C85.2@30.118,110.016 C84.2@28.943,110.016 ; U9.2@32.468,107.816 32.406,107.878 C80.2@30.293,107.878 30.206,107.791 C81.2@28.968,107.791 ; U9.7@32.468,114.166 C86.2@30.168,114.166 30.168,114.664 v2(31.04,115.536) 31.14,115.436 U9.8@32.468,115.436 ; C84.2@28.943,110.016 v2(28.943,109.086) 28.943,107.816 C81.2@28.968,107.791
  Bottom Layer w0.7: J6.3@102.935,118.92 102.935,116.988 103.875,116.048 R20.2@103.875,115.15
  other v2: 59.905,105.6 59.905,106.87 102.47,116.166
BIAS_HS_12V: BIAS_HS_12V.1 D4.2
BIAS_VIN: BIAS_VIN.1 C52.1 D4.1 D5.1 J1.7 J1.9 R92.2 R97.2 U3.10 | length 205.6
  Top Layer w0.254: v2(161.95,118.725) R97.2@161.975,117.45 ; U3.10@201.8,99.425 201.8,101.933 C52.1@202.2,102.333 205.553,105.685 ; R92.2@206.496,103.453 206.496,104.742 205.553,105.685 ; v1(209.749,107.874) 208.19,106.315 206.183,106.315 205.553,105.685
  Top Layer w1: D4.1@49.465,119.325 49.5,119.36 v1(49.5,120.875) ; D5.1@209.36,109.833 D5.1@209.436,109.757 209.436,108.188 v1(209.749,107.874)
  Layer 3 w1: v1(49.5,120.875) 56.95,128.325 141.95,128.325 BIAS_VIN.1@142.65,127.625 142.65,118.825 142.55,118.725 ; v2(134.596,118.725) v2(135.86,118.725) 142.55,118.725 ; v1(209.749,107.874) 186.762,107.874 v2(183.191,111.445) 175.911,118.725 v2(161.95,118.725) 142.55,118.725
CAN_FLT: J8.69 U3.8 | length 76.5
  Top Layer w0.254: J8.69@177.754,42.006 183.841,42.006 192.209,50.373 192.209,96.85 193.472,98.113 202.173,98.113 202.8,98.741 U3.8@202.8,99.425
CAN_WAKE: R71.1 R93.1 | length 1.4
  Top Layer w0.254: R71.1@203.834,100.822 R93.1@205.261,100.822
CANH_BUS: D3.2 J10.7 L2.4 R21.1 R22.2 | length 23.7
  Top Layer w0.254: R22.2@197.479,107.546 R21.1@197.479,109.121 197.629,108.971 L2.4@199.479,108.971 199.479,110.704 200.402,111.627 200.402,119.832 202.505,121.935 J10.7@203.139,121.935
  Bottom Layer w0.254: J10.7@203.139,121.935 203.175,121.899 D3.2@203.175,116.775
CANL_BUS: D3.1 J10.2 L2.3 R17.2 R18.2 | length 16.3
  Top Layer w0.254: J10.2@201.754,119.095 201.706,119.048 201.706,111.007 201.979,110.734 L2.3@201.979,108.971 203.879,108.971 203.954,109.046 R17.2@203.954,107.496
  Bottom Layer w0.5: D3.1@201.275,116.775 201.275,118.617 J10.2@201.754,119.095
DAC1: J8.9
DAC2: J8.14
DEBUG1: J18.3 R53.1 R64.1 | length 94.5
  Top Layer w0.254: J18.3@175.987,126.025 190.315,111.697 190.315,86.34 188.538,84.563 v2(185.822,84.563) R53.1@183.982,84.563 ; R64.1@183.424,45.206 185.519,45.206 v2(185.644,45.08)
  Layer 2 w0.254: v2(185.644,45.08) 185.644,48.595 185.822,48.773 v2(185.822,84.563)
DEBUG1_ALT: J8.77 R64.2 | length 4.5
  Top Layer w0.254: J8.77@177.754,45.206 R64.2@182.224,45.206
DEBUG1_MCU: J9.125 R53.2 | length 5
  Top Layer w0.254: J9.125@177.754,84.563 R53.2@182.782,84.563
DEBUG2: J8.59 J18.4 | length 104.2
  Top Layer w0.254: J18.4@173.447,126.025 175.009,124.463 176.396,124.463 189.545,111.314 189.545,86.662 188.246,85.363 v2(187.067,85.363) ; J8.59@177.754,38.006 v2(183.029,38.006)
  Layer 2 w0.254: v2(183.029,38.006) 186.525,41.501 186.525,83.902 187.067,84.444 v2(187.067,85.363)
DGND: C2.2 C11.2 C12.2 C14.2 C15.2 C16.2 C17.2 C25.2 C26.2 C27.2 C28.2 C31.2 C32.2 C33.2 C34.2 C36.2 C37.2 C38.2 C39.2 C40.2 C43.2 C48.2 C49.2 C50.2 C57.2 C58.2 C59.2 C60.2 C61.2 C62.2 C63.2 C64.2 C65.2 C66.2 C67.2 C68.2 DGND.1 pad.1@0.175,125.325 pad.1@228.15,87.475 pad.1@243.05,4.7 pad.1@243.15,125.725 pad.1@-0.2,4.75 pad.2@136.525,87.475 R11.1 R33.2 R73.1 R74.1 R77.2 | length 217.9
  Top Layer w1: v1(216.764,97.96) R11.1@216.764,100.842
  Layer 3 w0.254: v2(122.915,60.703) 121.926,61.691 121.926,63.674 135.252,77 176.925,77 177.1,77.175 177.1,77.69 176.89,77.9 139.7,77.9 136.725,80.875 pad.2@136.725,87.475 ; v2(122.915,63.241) 135.823,76.15 215.328,76.15 v1(216.775,77.597)
  Bottom Layer w0.254: R73.1@121.805,60.672 122.884,60.672 v2(122.915,60.703) ; R74.1@121.808,63.211 121.839,63.241 v2(122.915,63.241)
  other v1: 209.05,44.952 218.5,44.952 242.95,44.952 207.3,45.782 210.75,45.782 216.75,45.782 220.2,45.782 241.2,45.782 244.65,45.782 207.3,48.026 210.75,48.026 216.75,48.026 220.2,48.026 241.2,48.026 244.65,48.026 209.05,48.907 218.5,48.907 242.95,48.907 134.564,50.471 135.664,50.471 158.672,50.684 146.527,50.717 147.627,50.717 134.564,51.353 135.664,51.353 158.672,51.566 146.527,51.599 147.627,51.599 146.527,53.79 147.627,53.79 134.564,53.999 135.664,53.999 158.672,54.212 146.527,54.672 147.627,54.672 134.564,54.881 135.664,54.881 158.672,55.094 146.527,56.891 147.627,56.891 134.614,57.071 135.714,57.071 158.722,57.284 146.527,57.773 147.627,57.773 134.614,57.953 135.714,57.953 158.722,58.166 134.564,60.172 135.664,60.172 146.477,60.185 147.577,60.185 158.672,60.385 134.564,61.054 135.664,61.054 146.477,61.067 147.577,61.067 158.672,61.267 209.05,62.125 218.5,62.125 242.95,62.125 207.3,62.954 216.75,62.954 220.2,62.954 241.2,62.954 244.65,62.954 207.3,65.198 210.75,65.198 216.75,65.198 220.2,65.198 241.2,65.198 244.65,65.198 209.05,66.079 218.5,66.079 242.95,66.079 220.661,76.284 221.935,76.284 223.208,76.284 224.636,76.284 225.91,76.284 227.183,76.284 228.611,76.284 229.885,76.284 231.158,76.284 232.636,76.284 233.91,76.284 235.183,76.284 236.586,76.284 237.86,76.284 239.133,76.284 240.686,76.284 241.959,76.284 243.232,76.284 216.775,76.294 218.048,76.294 219.322,76.294 218.048,77.597 219.322,77.597 220.661,77.587 221.935,77.587 223.208,77.587 224.636,77.587 225.91,77.587 227.183,77.587 228.611,77.587 229.885,77.587 231.158,77.587 232.636,77.587 233.91,77.587 235.183,77.587 236.586,77.587 237.86,77.587 239.133,77.587 240.686,77.587 241.959,77.587 243.232,77.587 216.775,78.9 218.048,78.9 219.322,78.9 220.661,78.89 221.935,78.89 223.208,78.89 224.636,78.89 225.91,78.89 227.183,78.89 228.611,78.89 229.885,78.89 231.158,78.89 232.636,78.89 233.91,78.89 235.183,78.89 236.586,78.89 237.86,78.89 239.133,78.89 240.686,78.89 241.959,78.89 243.232,78.89 216.816,80.247 218.09,80.247 219.363,80.247 236.575,80.247 237.848,80.247 239.122,80.247 240.649,80.247 241.923,80.247 243.196,80.247 216.816,81.55 218.09,81.55 219.363,81.55 236.575,81.55 237.848,81.55 239.122,81.55 240.649,81.55 241.923,81.55 243.196,81.55 216.75,82.969 218.023,82.969 219.297,82.969 236.6,82.969 237.873,82.969 239.147,82.969 240.674,82.969 241.948,82.969 243.221,82.969 216.75,84.272 218.023,84.272 219.297,84.272 236.6,84.272 237.873,84.272 239.147,84.272 240.674,84.272 241.948,84.272 243.221,84.272 216.75,85.575 218.023,85.575 219.297,85.575 236.6,85.575 237.873,85.575 239.147,85.575 240.674,85.575 241.948,85.575 243.221,85.575 216.75,87.119 218.023,87.119 219.297,87.119 236.575,87.119 237.848,87.119 239.122,87.119 240.649,87.119 241.923,87.119 243.196,87.119 216.75,88.422 218.023,88.422 219.297,88.422 236.575,88.422 237.848,88.422 239.122,88.422 240.649,88.422 241.923,88.422 243.196,88.422 216.75,89.725 218.023,89.725 219.297,89.725 236.575,89.725 237.848,89.725 239.122,89.725 240.649,89.725 241.923,89.725 243.196,89.725 216.711,91.294 217.985,91.294 219.258,91.294 236.6,91.294 237.873,91.294 239.147,91.294 240.674,91.294 241.948,91.294 243.221,91.294 216.711,92.597 217.985,92.597 219.258,92.597 236.6,92.597 237.873,92.597 239.147,92.597 240.674,92.597 241.948,92.597 243.221,92.597 216.711,93.9 217.985,93.9 219.258,93.9 236.6,93.9 237.873,93.9 239.147,93.9 240.674,93.9 241.948,93.9 243.221,93.9 216.764,95.353 218.037,95.353 219.311,95.353 220.65,95.344 221.923,95.344 223.197,95.344 224.625,95.344 225.898,95.344 227.172,95.344 228.6,95.344 229.873,95.344 231.147,95.344 232.625,95.344 233.898,95.344 235.172,95.344 236.575,95.344 237.848,95.344 239.122,95.344 240.674,95.344 241.948,95.344 243.221,95.344 216.764,96.657 218.037,96.657 219.311,96.657 220.65,96.647 221.923,96.647 223.197,96.647 224.625,96.647 225.898,96.647 227.172,96.647 228.6,96.647 229.873,96.647 231.147,96.647 232.625,96.647 233.898,96.647 235.172,96.647 236.575,96.647 237.848,96.647 239.122,96.647 240.674,96.647 241.948,96.647 243.221,96.647 220.65,97.95 221.923,97.95 223.197,97.95 224.625,97.95 225.898,97.95 227.172,97.95 228.6,97.95 229.873,97.95 231.147,97.95 232.625,97.95 233.898,97.95 235.172,97.95 236.575,97.95 237.848,97.95 239.122,97.95 240.674,97.95 241.948,97.95 243.221,97.95 218.037,97.96 219.311,97.96
  other v2: 85.194,3.965 85.832,3.965 85.194,5.175 85.832,5.179 85.194,6.065 85.832,6.065
EN_5V0: J3.7 J8.72 | length 110.7
  Top Layer w0.254: 167.545,46.844 167.545,46.024 168.244,45.325 169.202,45.325 171.721,42.806 J8.72@174.354,42.806
  Layer 2 w0.254: v2(120.814,118.725) 120.814,117.79 121.104,117.5 139.575,117.5 141.125,115.95 141.125,107.005 167.379,80.751 167.379,47.311 v2(167.545,47.145)
EN_12V: J3.5 J8.74 | length 111.7
  Top Layer w0.254: v2(168.437,46.24) 169.141,46.24 171.776,43.606 J8.74@174.354,43.606
  Layer 2 w0.254: v2(119.55,118.725) 119.55,117.762 120.512,116.8 139.325,116.8 140.5,115.625 140.5,106.751 165.996,81.256 165.996,47.129 166.884,46.24 v2(168.437,46.24)
EN_ACL: J8.70 J17.8 | length 104
  Top Layer w0.254: v3(128.856,102.674) 128.856,107.386 130.232,108.762 142.707,108.762 156.723,94.746 156.723,74.827 166.7,64.85 166.7,45.877 167.868,44.709 168.794,44.709 171.497,42.006 J8.70@174.354,42.006
  Bottom Layer w0.254: v3(128.856,102.674) J17.8@131.675,102.674
EN_CAN: J8.67 U3.6 | length 76.1
  Top Layer w0.254: J8.67@177.754,41.206 183.865,41.206 192.725,50.065 192.725,96.509 193.777,97.562 202.132,97.562 202.3,97.394 U3.6@202.3,96.425
EN_SR: J8.68 J17.7 | length 85
  Top Layer w0.254: v2(167.655,43.606) 169.008,43.606 171.408,41.206 J8.68@174.354,41.206
  Layer 2 w0.254: v2(143.655,102.695) 165.204,81.146 165.204,46.057 v2(167.655,43.606)
  Bottom Layer w0.254: J17.7@135.36,102.695 v2(143.655,102.695)
ERRORSTS: J9.178 U14.9 U14.12 | length 147.2
  Top Layer w0.254: v2(120.546,24.605) 125.55,29.609 125.55,112.1 v2(126.575,113.125)
  Top Layer w0.5: v2(171.645,105.363) J9.178@174.354,105.363
  Layer 3 w0.254: v2(126.575,113.125) 165.524,113.125 171.645,107.004 v2(171.645,105.363)
  Bottom Layer w0.254: U14.12@119.377,22.833 120.398,22.833 120.723,23.158 120.723,24.428 v2(120.546,24.605) 120.368,24.783 U14.9@119.377,24.783
GaN_FAULT: C69.1 D1.2 J8.102 R34.2 | length 109.4
  Top Layer w0.254: v2(114.804,6.207) 114.804,5.373 D1.2@114.892,5.285 ; v2@171.436,54.936 v2(171.567,54.806) J8.102@174.354,54.806
  Layer 2 w0.254: v2(116.42,35.075) 117.445,36.1 169.514,36.1 172.173,38.759 172.173,52.841 171.567,53.447 v2(171.567,54.806)
  Layer 3 w0.254: v2(114.804,6.207) 115.676,7.079 115.676,34.331 v2(116.42,35.075)
  Bottom Layer w0.254: C69.1@114.912,34.224 R34.2@116.427,34.224 116.42,34.232 v2(116.42,35.075)
GaN_OC_1: D14.1 J8.94 | length 4.2
  Top Layer w0.254: D14.1@170.206,51.566 174.314,51.566 J8.94@174.354,51.606
GaN_OC_2: D12.1 J8.100 | length 85.8
  Top Layer w0.254: v2(170.598,54.006) J8.100@174.354,54.006
  Layer 3 w0.254: v2(122.22,48.843) 121.299,49.764 117.167,49.764 114.062,52.869 112.429,52.869 111.728,52.169 111.728,51.267 118.212,44.784 119.192,44.784 121.516,42.46 156.405,42.46 167.951,54.006 v2(170.598,54.006)
  Bottom Layer w0.254: v2(122.22,48.843) 122.226,48.849 D12.1@122.226,50.224
GS0: R46.2 R49.2 U10.5 | length 4
  Bottom Layer w0.254: R46.2@112.052,64.86 R49.2@113.258,64.86 114.265,64.86 114.906,64.219 U10.5@115.823,64.219
GS1: R41.2 R48.1 U10.6 | length 5.6
  Bottom Layer w0.254: R41.2@112.074,63.422 113.222,63.422 R48.1@113.301,63.502 114.69,63.502 115.248,62.944 115.97,62.944 116.473,63.446 U10.6@116.473,64.219
I_HV_1: C77.1 J8.11 R40.2 | length 167
  Top Layer w0.254: J8.11@177.754,15.606 180.169,15.606 180.525,15.25 180.525,4.41 v2(179.675,3.56)
  Layer 4 w0.254: v2(35.05,11.15) 42.446,11.15 44.33,13.034 89.441,13.034 92.268,10.207 158.525,10.207 165.173,3.56 v2(179.675,3.56)
  Bottom Layer w0.254: v2(35.05,11.15) C77.1@35.05,12.39
  Bottom Layer w0.5: R40.2@35.003,13.793 35.05,13.746 C77.1@35.05,12.39
I_HV_2: C30.1 J8.12 R27.2 | length 148.5
  Top Layer w0.254: v2(119.433,81.463) 115.888,81.463 107.177,72.752 107.177,14.569 112.388,9.358 118.754,9.358 148.433,9.358 150.025,10.949 165.002,10.949 169.658,15.606 J8.12@174.354,15.606
  Bottom Layer w0.254: R27.2@118.874,83.772 118.874,82.687 C30.1@118.854,82.668 119.433,82.089 v2(119.433,81.463)
I_HV_FAULT: C104.1 R63.1 R72.2 R115.2 | length 203.5
  Top Layer w0.254: v2(168.227,59.468) R72.2@169.056,59.468 ; v2(183.424,43.225) R63.1@183.424,44.161
  Layer 2 w0.254: v2(38.586,15.925) 41.6,15.925 42.76,14.765 80.99,14.765 103.51,37.285 168.729,37.285 170.95,39.507 170.95,47.794 169.611,49.133 169.611,52.654 168.227,54.038 v2(168.227,59.468)
  Layer 3 w0.254: v2(168.227,59.468) 172.248,59.468 176.345,55.371 186.038,55.371 187.935,53.474 187.935,48.468 183.424,43.956 v2(183.424,43.225)
  Bottom Layer w0.254: R115.2@37.547,18.4 37.547,17.752 37.725,17.573 C104.1@37.725,16.925 37.725,16.28 38.08,15.925 v2(38.586,15.925)
I_HV_FAULT_ALT: J8.75 R63.2 | length 4.6
  Top Layer w0.254: J8.75@177.754,44.406 181.06,44.406 181.305,44.161 R63.2@182.224,44.161
I_HV_FAULT_MCU: J8.110 R72.1 | length 4.7
  Top Layer w0.254: R72.1@170.256,59.468 171.718,58.006 J8.110@174.354,58.006
I_HV_FILTER: C51.1 J8.28 R67.2 | length 125.3
  Top Layer w0.254: v2(125.968,17.15) 130.719,12.399 147.075,12.399 148.931,14.256 162.344,14.256 170.094,22.006 J8.28@174.354,22.006
  Bottom Layer w0.254: C51.1@121.541,86.252 121.51,86.221 R67.2@121.51,84.878 121.51,83.795 v2(121.619,83.686) 125.3,80.005 125.3,17.818 v2(125.968,17.15)
I_HV_OC: C100.1 R12.1 R57.2 R110.2 | length 203.8
  Top Layer w0.254: R57.2@169.056,57.058 169.308,57.311 v2(169.308,57.848) ; R12.1@183.424,46.24 184.455,46.24 v2(184.47,46.256)
  Layer 2 w0.254: v2(33.68,9.781) 40.79,9.781 44.968,13.959 81.359,13.959 104.075,36.675 169.079,36.675 171.567,39.162 171.567,48.054 170.273,49.347 170.273,52.885 169.308,53.85 v2(169.308,57.848)
  Layer 3 w0.254: v2(169.308,57.848) 172.644,57.848 175.839,54.653 185.631,54.653 187.325,52.959 187.325,49.11 v2(184.47,46.256)
  Bottom Layer w0.254: C100.1@33.463,12.323 33.463,10.855 33.68,10.638 v2(33.68,9.781)
  Bottom Layer w0.5: C100.1@33.463,12.323 33.733,12.593 R110.2@33.733,13.793
I_HV_OC_ALT: J8.79 R12.2 | length 4.6
  Top Layer w0.254: J8.79@177.754,46.006 180.823,46.006 181.058,46.24 R12.2@182.224,46.24
I_HV_OC_MCU: J8.108 R57.1 | length 4.2
  Top Layer w0.254: R57.1@170.256,57.058 170.403,57.206 J8.108@174.354,57.206
I_LV_1: C94.1 J8.21 R62.2 R91.2 | length 215.1
  Top Layer w0.254: J8.21@177.754,19.606 180.419,19.606 181.825,18.2 181.825,3.9 v2(182.165,3.56) ; R91.2@187.067,105.615 188.101,105.615 v2(188.125,105.639)
  Layer 2 w0.254: v2(182.165,3.56) 190.521,11.916 190.521,70.627 204.908,85.014 204.908,102.542 201.811,105.639 v2(188.125,105.639)
  Bottom Layer w0.254: R62.2@120.05,16.458 120.05,15.279 C94.1@120.091,15.238 123.814,15.238 128.823,10.229 139.43,10.229 ; 139.45,10.229 169.296,10.229 174.5,5.025 180.699,5.025 v2(182.165,3.56)
I_LV_2: C54.1 J8.24 R76.2 R95.2 | length 255.1
  Top Layer w0.254: v2(113.082,58.836) 108.655,54.408 108.655,15.483 112.982,11.156 148.148,11.156 149.647,12.656 v2(162.956,12.656) 163.174,12.656 170.924,20.406 J8.24@174.354,20.406 ; R95.2@187.113,102.972 188.076,102.972 v2(188.125,103.021)
  Layer 2 w0.254: v2(162.956,12.656) 164.423,14.123 186.846,14.123 189.785,17.062 189.785,71.048 204.257,85.519 204.257,100.593 201.829,103.021 v2(188.125,103.021)
  Bottom Layer w0.254: C54.1@113.066,61.055 R76.2@113.066,59.791 113.082,59.774 v2(113.082,58.836)
"ISO 5V": C95.1 D10.1 R30.2 R37.2 U12.1 | length 9
  Top Layer w0.254: R30.2@27.852,118.732 R37.2@27.852,117.132 27.852,115.44 D10.1@27.847,115.436 27.847,114.664 28.361,114.151 C95.1@30.168,114.151 30.188,114.171 U12.1@32.568,114.171
LAG_EN_DRV: J20.6 U14.6 | length 75.2
  Bottom Layer w0.254: J20.6@56.457,6.065 54.565,6.065 54.05,5.55 54.05,2.577 55.256,1.371 64.019,1.371 87.43,24.783 U14.6@113.477,24.783
LAG_EN_DRV_MCU: J8.95 U14.5 | length 92.4
  Top Layer w0.254: J8.95@177.754,52.406 180.213,52.406 v2(181.4,53.593)
  Layer 2 w0.254: v2(111.921,23.967) 113.31,23.967 123.669,34.325 170.45,34.325 180.644,44.519 180.644,52.837 v2(181.4,53.593)
  Bottom Layer w0.254: v2(111.921,23.967) 112.087,24.133 U14.5@113.477,24.133
LAG_EN_ISO_12V: J3.3 J20.8 U14.11 | length 184.9
  Top Layer w0.254: v2(117.83,23.483) 124.811,30.464 124.811,110.35 118.28,116.881 v2(118.28,118.725)
  Bottom Layer w0.254: J20.8@56.457,7.335 54.05,7.335 53.25,6.534 53.25,2.188 54.684,0.754 64.379,0.754 83.95,20.325 114.672,20.325 v2(117.83,23.483) U14.11@119.377,23.483
LAG_EN_ISO_12V_MCU: J8.93 U14.13 | length 86.3
  Top Layer w0.254: J8.93@177.754,51.606 181.064,51.606 v2(181.51,52.052)
  Layer 2 w0.254: v2(117.719,22.015) 120.428,22.015 132.063,33.65 170.65,33.65 181.51,44.51 v2(181.51,52.052)
  Bottom Layer w0.254: v2(117.719,22.015) 117.887,22.183 U14.13@119.377,22.183
LAG_GaN_FAULT: J20.5 U4.1 | length 65.2
  Layer 3 w0.254: v2(60.143,6.065) 67.818,6.065 92.247,30.493 v2(114.195,30.493)
  Bottom Layer w0.254: v2(114.195,30.493) U4.1@115.197,30.493
LAG_HS_PWM: J8.53 J20.12 | length 175.5
  Top Layer w0.254: J8.53@177.754,32.406 182.189,32.406 186.425,28.17 186.425,5.981 v2(188.846,3.56)
  Layer 4 w0.254: v3(56.457,9.875) 56.457,10.606 56.768,10.916 85.884,10.916 96,0.8 187.55,0.8 188.846,2.096 v2(188.846,3.56)
LAG_HS_TEMP: J20.1 U1.15 U2.15 | length 93
  Bottom Layer w0.254: J20.1@60.143,3.525 61.508,3.525 62.19,4.207 62.19,4.859 102.6,45.269 ; U2.15@115.087,44.769 114.195,44.769 113.695,45.269 102.6,45.269 ; U1.15@115.139,53.869 104.244,53.869 102.6,52.225 102.6,45.269
LAG_ISO_12V_L: J6.9 J11.3 pad.3@57.665,50.375 | length 101.2
  Layer 2 w0.5: v2(56.66,50.375) 56.66,51.105 57.158,51.603 66.653,51.603 110.638,95.587 110.638,112.363 109.285,113.715 109.285,116.391 110.482,117.588 110.482,118.606 109.977,119.111 v2(106.745,119.111)
LAG_ISO_-5V_L: J6.13 J11.5 pad.3@57.665,49.105 | length 98.8
  Layer 2 w0.5: v2(56.66,49.105) 56.043,49.105 55.475,49.673 55.475,51.603 56.397,52.525 66.143,52.525 109.746,96.128 109.746,111.742 108.402,113.086 108.402,117.082 v2(109.285,117.966)
LAG_LS_PWM: J8.55 J20.10 | length 191.5
  Top Layer w0.254: J8.55@177.754,33.206 183.258,33.206 187.575,28.889 187.575,6.193 v2(190.208,3.56)
  Layer 3 w0.254: v3(56.457,8.605) 56.457,2.754 56.859,2.353 66.738,2.353 74.781,10.396 74.797,10.38 84.87,10.38 93.45,1.8 142.161,1.8 150.467,10.106 157.225,10.106 162.11,5.221 189.664,5.221 190.208,4.676 v2(190.208,3.56)
LAG_LS_TEMP: J20.3 U1.11 U2.11 | length 85.6
  Layer 2 w0.254: v2(110.547,50.993) 109.694,50.14 109.694,45.585 111.808,43.471 v2(111.808,42.269)
  Layer 3 w0.254: v2(60.143,4.795) 60.176,4.761 v3(63.15,4.761)
  Bottom Layer w0.254: v3(63.15,4.761) 100.658,42.269 v2(111.808,42.269) 113.695,42.269 114.195,42.769 U2.11@115.087,42.769 ; v2(110.547,50.993) 112.935,50.993 113.811,51.869 U1.11@115.139,51.869
LAG_OC_H: J20.4 U1.2 U2.2 | length 113.4
  Bottom Layer w0.254: J20.4@56.457,4.795 55.032,4.795 54.797,4.56 54.797,2.941 55.717,2.022 63.687,2.022 99.666,38 120.874,38 123.254,40.381 123.254,45.449 ; U2.2@118.087,44.769 119.313,44.769 119.938,45.394 123.199,45.394 123.254,45.449 ; U1.2@118.139,53.869 118.849,53.869 119.938,54.958 122.784,54.958 123.254,54.488 123.254,45.449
